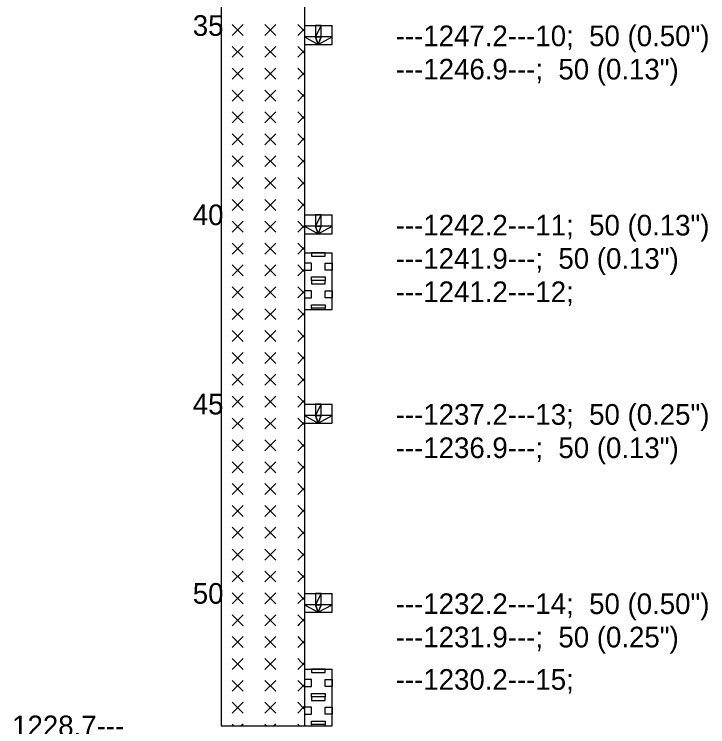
# Model space of a CAD drawing. Extents: x 2150161.5 to 2150203.1, y 143779.5 to 143868.5.
# Drawn here: x 2150175.114 to 2150179.278, y 143816.945 to 143821.223 of the extents above; entities that cross this region are included whole.
import ezdxf

# ---------------------------------------------------------------- set-up
doc = ezdxf.new("R2010")
doc.units = 0
doc.layers.add('Default', color=7, linetype='Continuous')

msp = doc.modelspace()

# ---------------------------------------------------------------- linework, layer by layer
at = {"layer": 'Default'}
for points in [[(2150176.3564, 143829.1095), (2150176.3564, 143816.9504)], [(2150176.8564, 143829.1095), (2150176.8564, 143816.9504)], [(2150176.4876, 143821.1609), (2150176.422, 143821.0953)], [(2150176.422, 143821.1609), (2150176.4876, 143821.0953)], [(2150176.6844, 143821.1609), (2150176.6188, 143821.0953)], [(2150176.6188, 143821.1609), (2150176.6844, 143821.0953)], [(2150176.8157, 143821.1609), (2150176.8564, 143821.1203)], [(2150176.8564, 143821.155), (2150177.023, 143821.155)], [(2150177.023, 143821.0413), (2150177.023, 143821.155)], [(2150176.8564, 143821.136), (2150176.8157, 143821.0953)], [(2150176.4876, 143821.0297), (2150176.422, 143820.9641)], [(2150176.422, 143821.0297), (2150176.4876, 143820.9641)], [(2150176.6844, 143821.0297), (2150176.6188, 143820.9641)], [(2150176.6188, 143821.0297), (2150176.6844, 143820.9641)], [(2150176.8157, 143821.0297), (2150176.8564, 143820.989)], [(2150176.8564, 143821.0413), (2150177.023, 143821.0413)], [(2150176.8564, 143821.0048), (2150176.8157, 143820.9641)], [(2150176.4876, 143820.8985), (2150176.422, 143820.8329)], [(2150176.422, 143820.8985), (2150176.4876, 143820.8329)], [(2150176.6844, 143820.8985), (2150176.6188, 143820.8329)], [(2150176.6188, 143820.8985), (2150176.6844, 143820.8329)], [(2150176.8157, 143820.8985), (2150176.8564, 143820.8578)], [(2150176.8564, 143820.8735), (2150176.8157, 143820.8329)], [(2150176.4876, 143820.7672), (2150176.422, 143820.7016)], [(2150176.422, 143820.7672), (2150176.4876, 143820.7016)], [(2150176.6844, 143820.7672), (2150176.6188, 143820.7016)], [(2150176.6188, 143820.7672), (2150176.6844, 143820.7016)], [(2150176.8157, 143820.7672), (2150176.8564, 143820.7266)], [(2150176.8564, 143820.7423), (2150176.8157, 143820.7016)], [(2150176.4876, 143820.636), (2150176.422, 143820.5704)], [(2150176.422, 143820.636), (2150176.4876, 143820.5704)], [(2150176.6844, 143820.636), (2150176.6188, 143820.5704)], [(2150176.6188, 143820.636), (2150176.6844, 143820.5704)], [(2150176.8157, 143820.636), (2150176.8564, 143820.5953)], [(2150176.8564, 143820.6111), (2150176.8157, 143820.5704)], [(2150176.4876, 143820.5048), (2150176.422, 143820.4392)], [(2150176.422, 143820.5048), (2150176.4876, 143820.4392)], [(2150176.6844, 143820.5048), (2150176.6188, 143820.4392)], [(2150176.6188, 143820.5048), (2150176.6844, 143820.4392)], [(2150176.8157, 143820.5048), (2150176.8564, 143820.4641)], [(2150176.8564, 143820.4798), (2150176.8157, 143820.4392)], [(2150176.4876, 143820.3735), (2150176.422, 143820.3079)], [(2150176.422, 143820.3735), (2150176.4876, 143820.3079)], [(2150176.6844, 143820.3735), (2150176.6188, 143820.3079)], [(2150176.6188, 143820.3735), (2150176.6844, 143820.3079)], [(2150176.8157, 143820.3735), (2150176.8564, 143820.3329)], [(2150176.8564, 143820.3486), (2150176.8157, 143820.3079)], [(2150176.4876, 143820.2423), (2150176.422, 143820.1767)], [(2150176.422, 143820.2423), (2150176.4876, 143820.1767)], [(2150176.6844, 143820.2423), (2150176.6188, 143820.1767)], [(2150176.6188, 143820.2423), (2150176.6844, 143820.1767)], [(2150176.8157, 143820.2423), (2150176.8564, 143820.2016)], [(2150176.8564, 143820.2174), (2150176.8157, 143820.1767)], [(2150176.4876, 143820.1111), (2150176.422, 143820.0455)], [(2150176.422, 143820.1111), (2150176.4876, 143820.0455)], [(2150176.6844, 143820.1111), (2150176.6188, 143820.0455)], [(2150176.6188, 143820.1111), (2150176.6844, 143820.0455)], [(2150176.8157, 143820.1111), (2150176.8564, 143820.0704)], [(2150176.8564, 143820.0861), (2150176.8157, 143820.0455)], [(2150176.8564, 143820.0186), (2150177.023, 143820.0186)], [(2150177.023, 143819.905), (2150177.023, 143820.0186)], [(2150176.4876, 143819.9798), (2150176.422, 143819.9142)], [(2150176.422, 143819.9798), (2150176.4876, 143819.9142)], [(2150176.6844, 143819.9798), (2150176.6188, 143819.9142)], [(2150176.6188, 143819.9798), (2150176.6844, 143819.9142)], [(2150176.8157, 143819.9798), (2150176.8564, 143819.9392)], [(2150176.8564, 143819.9549), (2150176.8157, 143819.9142)], [(2150176.8564, 143819.905), (2150177.023, 143819.905)], [(2150176.4876, 143819.8486), (2150176.422, 143819.783)], [(2150176.422, 143819.8486), (2150176.4876, 143819.783)], [(2150176.6844, 143819.8486), (2150176.6188, 143819.783)], [(2150176.6188, 143819.8486), (2150176.6844, 143819.783)], [(2150176.8157, 143819.8486), (2150176.8564, 143819.8079)], [(2150176.8564, 143819.8237), (2150176.8157, 143819.783)], [(2150176.8564, 143819.7913), (2150177.023, 143819.7913)], [(2150177.023, 143819.4504), (2150177.023, 143819.7913)], [(2150176.4876, 143819.7174), (2150176.422, 143819.6518)], [(2150176.422, 143819.7174), (2150176.4876, 143819.6518)], [(2150176.6844, 143819.7174), (2150176.6188, 143819.6518)], [(2150176.6188, 143819.7174), (2150176.6844, 143819.6518)], [(2150176.8157, 143819.7174), (2150176.8564, 143819.6767)], [(2150176.8564, 143819.6924), (2150176.8157, 143819.6518)], [(2150176.4876, 143819.5861), (2150176.422, 143819.5205)], [(2150176.422, 143819.5861), (2150176.4876, 143819.5205)], [(2150176.6844, 143819.5861), (2150176.6188, 143819.5205)], [(2150176.6188, 143819.5861), (2150176.6844, 143819.5205)], [(2150176.8157, 143819.5861), (2150176.8564, 143819.5455)], [(2150176.8564, 143819.5612), (2150176.8157, 143819.5205)], [(2150176.4876, 143819.4549), (2150176.422, 143819.3893)], [(2150176.422, 143819.4549), (2150176.4876, 143819.3893)], [(2150176.6844, 143819.4549), (2150176.6188, 143819.3893)], [(2150176.6188, 143819.4549), (2150176.6844, 143819.3893)], [(2150176.8157, 143819.4549), (2150176.8564, 143819.4142)], [(2150176.8564, 143819.4504), (2150177.023, 143819.4504)], [(2150176.8564, 143819.43), (2150176.8157, 143819.3893)], [(2150176.4876, 143819.3237), (2150176.422, 143819.2581)], [(2150176.422, 143819.3237), (2150176.4876, 143819.2581)], [(2150176.6844, 143819.3237), (2150176.6188, 143819.2581)], [(2150176.6188, 143819.3237), (2150176.6844, 143819.2581)], [(2150176.8157, 143819.3237), (2150176.8564, 143819.283)], [(2150176.8564, 143819.2987), (2150176.8157, 143819.2581)], [(2150176.4876, 143819.1924), (2150176.422, 143819.1268)], [(2150176.422, 143819.1924), (2150176.4876, 143819.1268)], [(2150176.6844, 143819.1924), (2150176.6188, 143819.1268)], [(2150176.6188, 143819.1924), (2150176.6844, 143819.1268)], [(2150176.8157, 143819.1924), (2150176.8564, 143819.1518)], [(2150176.8564, 143819.1675), (2150176.8157, 143819.1268)], [(2150176.4876, 143819.0612), (2150176.422, 143818.9956)], [(2150176.422, 143819.0612), (2150176.4876, 143818.9956)], [(2150176.6844, 143819.0612), (2150176.6188, 143818.9956)], [(2150176.6188, 143819.0612), (2150176.6844, 143818.9956)], [(2150176.8157, 143819.0612), (2150176.8564, 143819.0205)], [(2150176.8564, 143819.0363), (2150176.8157, 143818.9956)], [(2150176.4876, 143818.93), (2150176.422, 143818.8644)], [(2150176.422, 143818.93), (2150176.4876, 143818.8644)], [(2150176.6844, 143818.93), (2150176.6188, 143818.8644)], [(2150176.6188, 143818.93), (2150176.6844, 143818.8644)], [(2150176.8157, 143818.93), (2150176.8564, 143818.8893)], [(2150176.8564, 143818.905), (2150176.8157, 143818.8644)], [(2150176.8564, 143818.8823), (2150177.023, 143818.8823)], [(2150177.023, 143818.7686), (2150177.023, 143818.8823)], [(2150176.4876, 143818.7987), (2150176.422, 143818.7331)], [(2150176.422, 143818.7987), (2150176.4876, 143818.7331)], [(2150176.6844, 143818.7987), (2150176.6188, 143818.7331)], [(2150176.6188, 143818.7987), (2150176.6844, 143818.7331)], [(2150176.8157, 143818.7987), (2150176.8564, 143818.7581)], [(2150176.8564, 143818.7738), (2150176.8157, 143818.7331)], [(2150176.8564, 143818.7686), (2150177.023, 143818.7686)], [(2150176.4876, 143818.6675), (2150176.422, 143818.6019)], [(2150176.422, 143818.6675), (2150176.4876, 143818.6019)], [(2150176.6844, 143818.6675), (2150176.6188, 143818.6019)], [(2150176.6188, 143818.6675), (2150176.6844, 143818.6019)], [(2150176.8157, 143818.6675), (2150176.8564, 143818.6268)], [(2150176.8564, 143818.6426), (2150176.8157, 143818.6019)], [(2150176.4876, 143818.5363), (2150176.422, 143818.4707)], [(2150176.422, 143818.5363), (2150176.4876, 143818.4707)], [(2150176.6844, 143818.5363), (2150176.6188, 143818.4707)], [(2150176.6188, 143818.5363), (2150176.6844, 143818.4707)], [(2150176.8157, 143818.5363), (2150176.8564, 143818.4956)], [(2150176.8564, 143818.5113), (2150176.8157, 143818.4707)], [(2150176.4876, 143818.405), (2150176.422, 143818.3394)], [(2150176.422, 143818.405), (2150176.4876, 143818.3394)], [(2150176.6844, 143818.405), (2150176.6188, 143818.3394)], [(2150176.6188, 143818.405), (2150176.6844, 143818.3394)], [(2150176.8157, 143818.405), (2150176.8564, 143818.3644)], [(2150176.8564, 143818.3801), (2150176.8157, 143818.3394)], [(2150176.4876, 143818.2738), (2150176.422, 143818.2082)], [(2150176.422, 143818.2738), (2150176.4876, 143818.2082)], [(2150176.6844, 143818.2738), (2150176.6188, 143818.2082)], [(2150176.6188, 143818.2738), (2150176.6844, 143818.2082)], [(2150176.8157, 143818.2738), (2150176.8564, 143818.2331)], [(2150176.8564, 143818.2489), (2150176.8157, 143818.2082)], [(2150176.4876, 143818.1426), (2150176.422, 143818.077)], [(2150176.422, 143818.1426), (2150176.4876, 143818.077)], [(2150176.6844, 143818.1426), (2150176.6188, 143818.077)], [(2150176.6188, 143818.1426), (2150176.6844, 143818.077)], [(2150176.8157, 143818.1426), (2150176.8564, 143818.1019)], [(2150176.8564, 143818.1176), (2150176.8157, 143818.077)], [(2150176.4876, 143818.0113), (2150176.422, 143817.9457)], [(2150176.422, 143818.0113), (2150176.4876, 143817.9457)], [(2150176.6844, 143818.0113), (2150176.6188, 143817.9457)], [(2150176.6188, 143818.0113), (2150176.6844, 143817.9457)], [(2150176.8157, 143818.0113), (2150176.8564, 143817.9707)], [(2150176.8564, 143817.9864), (2150176.8157, 143817.9457)], [(2150176.4876, 143817.8801), (2150176.422, 143817.8145)], [(2150176.422, 143817.8801), (2150176.4876, 143817.8145)], [(2150176.6844, 143817.8801), (2150176.6188, 143817.8145)], [(2150176.6188, 143817.8801), (2150176.6844, 143817.8145)], [(2150176.8157, 143817.8801), (2150176.8564, 143817.8394)], [(2150176.8564, 143817.8552), (2150176.8157, 143817.8145)], [(2150176.4876, 143817.7489), (2150176.422, 143817.6833)], [(2150176.422, 143817.7489), (2150176.4876, 143817.6833)], [(2150176.6844, 143817.7489), (2150176.6188, 143817.6833)], [(2150176.6188, 143817.7489), (2150176.6844, 143817.6833)], [(2150176.8157, 143817.7489), (2150176.816, 143817.7486), (2150176.8564, 143817.7082)], [(2150176.8564, 143817.7239), (2150176.8191, 143817.6867), (2150176.8157, 143817.6833)], [(2150176.8564, 143817.7459), (2150177.023, 143817.7459)], [(2150177.023, 143817.6323), (2150177.023, 143817.7459)], [(2150176.4876, 143817.6176), (2150176.422, 143817.552)], [(2150176.422, 143817.6176), (2150176.4876, 143817.552)], [(2150176.6844, 143817.6176), (2150176.6188, 143817.552)], [(2150176.6188, 143817.6176), (2150176.6844, 143817.552)], [(2150176.8157, 143817.6176), (2150176.823, 143817.6103), (2150176.8564, 143817.577)], [(2150176.8564, 143817.6323), (2150177.023, 143817.6323)], [(2150176.8564, 143817.5927), (2150176.8254, 143817.5618), (2150176.8157, 143817.552)], [(2150176.4876, 143817.4864), (2150176.422, 143817.4208)], [(2150176.422, 143817.4864), (2150176.4876, 143817.4208)], [(2150176.6844, 143817.4864), (2150176.6188, 143817.4208)], [(2150176.6188, 143817.4864), (2150176.6844, 143817.4208)], [(2150176.8157, 143817.4864), (2150176.83, 143817.4721), (2150176.8564, 143817.4457)], [(2150176.8564, 143817.4615), (2150176.8318, 143817.4369), (2150176.8157, 143817.4208)], [(2150176.4876, 143817.3552), (2150176.422, 143817.2896)], [(2150176.422, 143817.3552), (2150176.4876, 143817.2896)], [(2150176.6844, 143817.3552), (2150176.6188, 143817.2896)], [(2150176.6188, 143817.3552), (2150176.6844, 143817.2896)], [(2150176.8157, 143817.3552), (2150176.837, 143817.3339), (2150176.8564, 143817.3145)], [(2150176.8564, 143817.3302), (2150176.8381, 143817.312), (2150176.8157, 143817.2896)], [(2150176.8564, 143817.2913), (2150177.023, 143817.2913)], [(2150177.023, 143816.9504), (2150177.023, 143817.2913)], [(2150176.4876, 143817.2239), (2150176.422, 143817.1583)], [(2150176.422, 143817.2239), (2150176.4876, 143817.1583)], [(2150176.6844, 143817.2239), (2150176.6188, 143817.1583)], [(2150176.6188, 143817.2239), (2150176.6844, 143817.1583)], [(2150176.8157, 143817.2239), (2150176.844, 143817.1957), (2150176.8564, 143817.1833)], [(2150176.8564, 143817.199), (2150176.8444, 143817.187), (2150176.8157, 143817.1583)], [(2150176.4876, 143817.0927), (2150176.422, 143817.0271)], [(2150176.422, 143817.0927), (2150176.4876, 143817.0271)], [(2150176.6844, 143817.0927), (2150176.6188, 143817.0271)], [(2150176.6188, 143817.0927), (2150176.6844, 143817.0271)], [(2150176.8157, 143817.0927), (2150176.8509, 143817.0574), (2150176.8564, 143817.052)], [(2150176.8564, 143817.0678), (2150176.8507, 143817.0621), (2150176.8157, 143817.0271)], [(2150176.422, 143816.9615), (2150176.433, 143816.9504)], [(2150176.4876, 143816.9615), (2150176.4766, 143816.9504)], [(2150176.6188, 143816.9615), (2150176.6299, 143816.9504)], [(2150176.6844, 143816.9615), (2150176.6734, 143816.9504)], [(2150176.8157, 143816.9615), (2150176.8267, 143816.9504)], [(2150176.3564, 143816.9504), (2150176.8564, 143816.9504)], [(2150176.8564, 143816.9504), (2150177.023, 143816.9504)]]:
    msp.add_lwpolyline(points, dxfattribs=at)
for points in [[(2150176.923, 143821.0868), (2150176.9564, 143821.0868), (2150176.9564, 143821.155), (2150176.923, 143821.0868)], [(2150176.923, 143821.0868), (2150176.9564, 143821.155), (2150176.923, 143821.155), (2150176.923, 143821.0868)], [(2150176.923, 143821.0868), (2150176.8564, 143821.0868), (2150176.9397, 143821.0413), (2150176.923, 143821.0868)], [(2150176.923, 143821.0868), (2150176.9397, 143821.0413), (2150176.9564, 143821.0868), (2150176.923, 143821.0868)], [(2150176.9397, 143821.0413), (2150177.023, 143821.0868), (2150176.9564, 143821.0868), (2150176.9397, 143821.0413)], [(2150176.923, 143819.9504), (2150176.9564, 143819.9504), (2150176.9564, 143820.0186), (2150176.923, 143819.9504)], [(2150176.923, 143819.9504), (2150176.9564, 143820.0186), (2150176.923, 143820.0186), (2150176.923, 143819.9504)], [(2150176.923, 143819.9504), (2150176.8564, 143819.9504), (2150176.9397, 143819.905), (2150176.923, 143819.9504)], [(2150176.923, 143819.9504), (2150176.9397, 143819.905), (2150176.9564, 143819.9504), (2150176.923, 143819.9504)], [(2150176.9397, 143819.905), (2150177.023, 143819.9504), (2150176.9564, 143819.9504), (2150176.9397, 143819.905)], [(2150176.898, 143819.7913), (2150176.898, 143819.7705), (2150176.9814, 143819.7705), (2150176.9814, 143819.7913)], [(2150176.8564, 143819.6872), (2150176.898, 143819.6872), (2150176.898, 143819.7288), (2150176.8564, 143819.7288)], [(2150177.023, 143819.6872), (2150176.9814, 143819.6872), (2150176.9814, 143819.7288), (2150177.023, 143819.7288)], [(2150176.898, 143819.6247), (2150176.898, 143819.6455), (2150176.9814, 143819.6455), (2150176.9814, 143819.6247)], [(2150176.898, 143819.6247), (2150176.898, 143819.6038), (2150176.9814, 143819.6038), (2150176.9814, 143819.6247)], [(2150176.8564, 143819.5205), (2150176.898, 143819.5205), (2150176.898, 143819.5622), (2150176.8564, 143819.5622)], [(2150177.023, 143819.5205), (2150176.9814, 143819.5205), (2150176.9814, 143819.5622), (2150177.023, 143819.5622)], [(2150176.898, 143819.458), (2150176.898, 143819.4788), (2150176.9814, 143819.4788), (2150176.9814, 143819.458)], [(2150176.9814, 143819.458), (2150176.898, 143819.458), (2150176.898, 143819.4504), (2150176.9814, 143819.4504)], [(2150176.923, 143818.8141), (2150176.9564, 143818.8141), (2150176.9564, 143818.8823), (2150176.923, 143818.8141)], [(2150176.923, 143818.8141), (2150176.9564, 143818.8823), (2150176.923, 143818.8823), (2150176.923, 143818.8141)], [(2150176.923, 143818.8141), (2150176.8564, 143818.8141), (2150176.9397, 143818.7686), (2150176.923, 143818.8141)], [(2150176.923, 143818.8141), (2150176.9397, 143818.7686), (2150176.9564, 143818.8141), (2150176.923, 143818.8141)], [(2150176.9397, 143818.7686), (2150177.023, 143818.8141), (2150176.9564, 143818.8141), (2150176.9397, 143818.7686)], [(2150176.923, 143817.6777), (2150176.9564, 143817.6777), (2150176.9564, 143817.7459), (2150176.923, 143817.6777)], [(2150176.923, 143817.6777), (2150176.9564, 143817.7459), (2150176.923, 143817.7459), (2150176.923, 143817.6777)], [(2150176.923, 143817.6777), (2150176.8564, 143817.6777), (2150176.9397, 143817.6323), (2150176.923, 143817.6777)], [(2150176.923, 143817.6777), (2150176.9397, 143817.6323), (2150176.9564, 143817.6777), (2150176.923, 143817.6777)], [(2150176.9397, 143817.6323), (2150177.023, 143817.6777), (2150176.9564, 143817.6777), (2150176.9397, 143817.6323)], [(2150176.898, 143817.2913), (2150176.898, 143817.2705), (2150176.9814, 143817.2705), (2150176.9814, 143817.2913)], [(2150176.8564, 143817.1872), (2150176.898, 143817.1872), (2150176.898, 143817.2288), (2150176.8564, 143817.2288)], [(2150177.023, 143817.1872), (2150176.9814, 143817.1872), (2150176.9814, 143817.2288), (2150177.023, 143817.2288)], [(2150176.898, 143817.1247), (2150176.898, 143817.1455), (2150176.9814, 143817.1455), (2150176.9814, 143817.1247)], [(2150176.898, 143817.1247), (2150176.898, 143817.1038), (2150176.9814, 143817.1038), (2150176.9814, 143817.1247)], [(2150176.8564, 143817.0205), (2150176.898, 143817.0205), (2150176.898, 143817.0622), (2150176.8564, 143817.0622)], [(2150177.023, 143817.0205), (2150176.9814, 143817.0205), (2150176.9814, 143817.0622), (2150177.023, 143817.0622)], [(2150176.898, 143816.958), (2150176.898, 143816.9788), (2150176.9814, 143816.9788), (2150176.9814, 143816.958)], [(2150176.9814, 143816.958), (2150176.898, 143816.958), (2150176.898, 143816.9504), (2150176.9814, 143816.9504)]]:
    msp.add_lwpolyline(points, close=True, dxfattribs=at)

# ---------------------------------------------------------------- texts
for s, p in [('35', (2150176.1859, 143821.093)), ('---1247.2---10;  50 (0.50")', (2150177.4044, 143821.031)), ('---1246.9---;  50 (0.13")', (2150177.4044, 143820.831)), ('40', (2150176.1859, 143819.9566)), ('---1242.2---11;  50 (0.13")', (2150177.4044, 143819.8946)), ('---1241.9---;  50 (0.13")', (2150177.4044, 143819.6946)), ('---1241.2---12;', (2150177.4044, 143819.4946)), ('45', (2150176.1859, 143818.8203)), ('---1237.2---13;  50 (0.25")', (2150177.4044, 143818.7583)), ('---1236.9---;  50 (0.13")', (2150177.4044, 143818.5583)), ('50', (2150176.1859, 143817.6839)), ('---1232.2---14;  50 (0.50")', (2150177.4044, 143817.6219)), ('---1231.9---;  50 (0.25")', (2150177.4044, 143817.4219)), ('---1230.2---15;', (2150177.4044, 143817.1673)), ('1228.7---', (2150175.1015, 143816.8884))]:
    msp.add_text(s, height=0.124, dxfattribs=at).set_placement(p)

doc.saveas('drawing.dxf')
